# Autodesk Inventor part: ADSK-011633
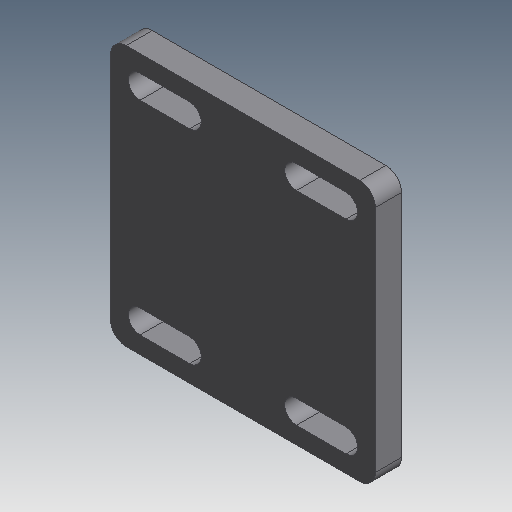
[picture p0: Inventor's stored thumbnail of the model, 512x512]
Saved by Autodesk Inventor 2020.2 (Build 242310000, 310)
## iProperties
Created: 2000-02
Part Number: ADSK-011633
Material: Pearson HRS
Document SubType Name: Modeling
Designer: sspink
Density: 7.83 g/cm^3
Appearance: Métal - Acier
Mass: 683.693 g
Surface Area: 247.881 cm^2
Volume: 87.3171 cm^3
Control State: 0
Checked Out: False
Master: False
Shininess: 0.0
Length Units: 11269
Angle Units: 11279
Time Units: 11290
Mass Units: 11283
Length Display Precision: 3
Angle Display Precision: 2
Compacted: True
Cutlength: 4
Material Desc: FLAT,HRS,0.38 X 4.00
Material_Number: A084411
Dimensions: 100x10x101,6 mm
Mass: 0,72 kg
VLT_Material: Pearson HRS
Density: 0.0
Volumn: 0.0
Area: 0.0
PropertySet Name: Model Information
Author: sspink
Revision Number: -
Title: ADSK-011633
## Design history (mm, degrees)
node "Solide1"
  node "Extrusion1" dims "d2" = 10, "d3" = 0
  node "Extrusion2" dims "d8" = 25.4, "d9" = 0
  node "Fillet1" dims "d16" = 6
sketch "Sketch1"
  geometry: L1 (-50.8, -50)-(50.8, -50); L2 (50.8, -50)-(50.8, 50); L3 (50.8, 50)-(-50.8, 50); L4 (-50.8, 50)-(-50.8, -50); 3 further points
  constraints: 8 end point, 2 midpoint, 2 parallel, 1 horizontal, 1 horizontal alignment, 1 perpendicular, 1 vertical alignment
  dimensions: "d0" = 100 distance between parallel lines of L1 L3; "d1" = 101.6 distance between parallel lines of L2 L4
sketch "Sketch2"
  geometry: L1 (-39.5, 43.5)-(-20.5, 43.5); L2 (-20.5, 43.5)-(-20.5, 34.5); L3 (-20.5, 34.5)-(-39.5, 34.5); L4 (-39.5, 34.5)-(-39.5, 43.5); L5 (-39.5, 39)-(-20.5, 39); L6 (30, -39)-(-30, -39); L7 (-30, -39)-(-30, 39); L8 (-30, 39)-(30, 39); L9 (30, 39)-(30, -39); L10 (30, -39)-(-30, 39); L11 (-30, -39)-(30, 39); L12 (-39.5, -43.5)-(-39.5, -34.5); L13 (-20.5, -43.5)-(-39.5, -43.5); L14 (-39.5, -39)-(-20.5, -39); L15 (-39.5, -34.5)-(-20.5, -34.5); L16 (-20.5, -34.5)-(-20.5, -43.5); L17 (20.5, -43.5)-(20.5, -34.5); L18 (39.5, -43.5)-(20.5, -43.5); L19 (20.5, -39)-(39.5, -39); L20 (20.5, -34.5)-(39.5, -34.5); L21 (39.5, -34.5)-(39.5, -43.5); L22 (20.5, 34.5)-(20.5, 43.5); L23 (39.5, 34.5)-(20.5, 34.5); L24 (20.5, 39)-(39.5, 39); L25 (20.5, 43.5)-(39.5, 43.5); L26 (39.5, 43.5)-(39.5, 34.5); A1 r 4.5 centre (-20.5, 39) between (-20.5, 34.5) and (-20.5, 43.5); A2 r 4.5 centre (-39.5, 39) between (-39.5, 43.5) and (-39.5, 34.5); A3 r 4.5 centre (-39.5, -39) between (-39.5, -34.5) and (-39.5, -43.5); A4 r 4.5 centre (-20.5, -39) between (-20.5, -43.5) and (-20.5, -34.5); A5 r 4.5 centre (20.5, -39) between (20.5, -34.5) and (20.5, -43.5); A6 r 4.5 centre (39.5, -39) between (39.5, -43.5) and (39.5, -34.5); A7 r 4.5 centre (20.5, 39) between (20.5, 43.5) and (20.5, 34.5); A8 r 4.5 centre (39.5, 39) between (39.5, 34.5) and (39.5, 43.5); 4 further points
  constraints: 52 end point, 16 point on circle, 10 parallel, 9 horizontal, 9 midpoint, 8 centre point, 8 tangent, 5 perpendicular
  dimensions: "d6" = 9 distance of L1.end L2.end; "d7" = 19 distance of L2.end L3.end; "d17" = 78 distance of L6.end L7.end; "d18" = 60 distance of L7.end L8.end; "d19" = 9 distance of L15.end L13.start; "d20" = 19 distance of L13.start L12.start; "d21" = 9 distance of L20.end L18.start; "d22" = 19 distance of L18.start L17.start; "d23" = 9 distance of L25.end L23.start; "d24" = 19 distance of L23.start L22.start
node "Corps solides"
node "Corps surfaciques"
